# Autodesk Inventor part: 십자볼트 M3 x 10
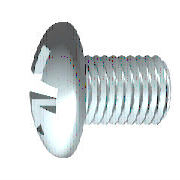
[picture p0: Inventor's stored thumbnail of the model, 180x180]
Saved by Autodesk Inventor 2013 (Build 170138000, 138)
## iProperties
IsCustomPart: 0
Created: 2012-02
Part Number: 십자볼트 M3 x 10
Material: 스테인리스강
Description: 십자 오목 머리 나사
Document SubType Name: Modeling
Standard: KS B 1023
Designer: mduedu
Standards Organization: KS
Language: ko-KR
Size Designation: A  M 3 x 10 - H
Categories: <MemberInstance><Categories><Category DisplayName="조임쇠" InternalName="e4da775c-781d-43d5-af7c-5136215cf5a6" Mnemonic="FSTN"><Category DisplayName="볼트" InternalN
Density: 1 g/cm^3
Author: mduedu
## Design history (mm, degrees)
body "Solid1"
workplane "Work Plane3"
sketch "스케치2"
  geometry: L1 (-3.72, 0)-(3.72, 0) reference; L2 (0, -3.72)-(0, 3.72) reference; L3 (0, 1.5)-(0, 0); L4 (0, 0)-(1.5, 0); L5 (0, 0)-(1.879, 1.879); L6 (0.253, 1.479)-(0.261, 0.456); L7 (1.479, 0.253)-(0.456, 0.261); L8 (0.253, -1.479)-(0.261, -0.456); L9 (1.479, -0.253)-(0.456, -0.261); L10 (-0.253, 1.479)-(-0.261, 0.456); L11 (-1.479, 0.253)-(-0.456, 0.261); L12 (-1.479, -0.253)-(-0.456, -0.261); L13 (-0.253, -1.479)-(-0.261, -0.456); A1 r 0.45 centre (0, 0) between (0.45, 0) and (0, 0.45); A2 r 1.5 centre (0, 0) between (1.5, 0) and (1.479, 0.253); A3 r 1.5 centre (0, 0) between (0.253, 1.479) and (0, 1.5); A4 r 1.5 centre (0, 0) between (1.479, 0.253) and (0.253, 1.479); A5 r 1.5 centre (0, 0) between (0, -1.5) and (0.253, -1.479); A6 r 1.5 centre (0, 0) between (0.253, -1.479) and (1.479, -0.253); A7 r 1.5 centre (0, 0) between (1.479, -0.253) and (1.5, 0); A8 r 1.5 centre (0, 0) between (-1.479, 0.253) and (-1.5, 0); A9 r 1.5 centre (0, 0) between (-0.253, 1.479) and (-1.479, 0.253); A10 r 1.5 centre (0, 0) between (0, 1.5) and (-0.253, 1.479); A11 r 1.5 centre (0, 0) between (-1.5, 0) and (-1.479, -0.253); A12 r 1.5 centre (0, 0) between (-1.479, -0.253) and (-0.253, -1.479); A13 r 1.5 centre (0, 0) between (-0.253, -1.479) and (0, -1.5); A14 r 0.525 centre (0, 0) between (0.525, 0) and (0, 0.525); A15 r 0.197 centre (0.457, 0.457) between (0.261, 0.456) and (0.456, 0.261); A16 r 0.197 centre (0.457, -0.457) between (0.456, -0.261) and (0.261, -0.456); A17 r 0.197 centre (-0.457, 0.457) between (-0.456, 0.261) and (-0.261, 0.456); A18 r 0.197 centre (-0.457, -0.457) between (-0.261, -0.456) and (-0.456, -0.261); 1 further point
  constraints: 38 point on circle, 22 end point, 19 symmetric about line, 18 centre point, 4 coincident, 3 collinear, 3 point on line, 3 tangent, 1 perpendicular, 21 other
  dimensions: "d4" = 45 deg angle of L5 L4; "d5" = 0.9 diameter of A1 (= 0.3 x SDM); "d6" = 3 diameter of A4 (= SDM); "d7" = 0.2525 distance from line of L6.start L3 (= 0.5 x SBR); "d14" = 1.05 diameter of A14 (= 0.35 x SDM)
extrude "슬롯" join sketch "스케치2" taper "d15" = 5 deg; stored distance "d54" = 10
revolve "절단부" stored, may be unused: angle "d56" = 90 deg
revolve "본체" stored, may be unused: angle "d18" = 90 deg
workplane "Work Plane1"
sketch "스케치1"
  geometry: L1 (10, 0)-(10, 1.5); L2 (10, 1.5)-(1, 1.5); L3 (3.962, 5.08)-(3.962, 5.08); L4 (-2.4, 0)-(-2.4, 2.59); L5 (-2.2, 1.4)-(-1.036, 0.82); L6 (-1.036, 0.82)-(-0.6, 0); L7 (-0.6, 0)-(10, 0); L8 (-5.105, 0)-(12.517, 0) reference; L9 (0, -1.016)-(0, 6.096) reference; L10 (-2.2, 1.4)-(-2.4, 1.5); L11 (-1.636, 2.657)-(-2.4, 2.59); L12 (-1.636, 2.657)-(0, 2.8); L13 (0, 2.8)-(0, 1.347); L14 (0, 1.347)-(0.693, 1.347); L15 (0.693, 1.347)-(1, 1.5); L16 (1, 1.5)-(0, 1.5); A1 r 5 centre (2.6, 0) between (-1.636, 2.657) and (-2.4, 0)
  constraints: 28 end point, 5 point on line, 4 collinear, 4 point on circle, 3 parallel, 2 perpendicular, 1 centre point, 1 horizontal, 1 tangent
  dimensions: "d1" = 3 diameter of L2 L7 (= GD); "d2" = 1.8 distance from line of L6.end L4 (= STI); "d11" = 3 diameter of L10.end L7 (= SDM); "d12" = 62 deg angle of L6 L7; "d13" = 26.5 deg angle of L5 L7; "d17" = 5.6 diameter of L12.end L7 (= KOD); "d19" = 5 deg angle of L12 L7 (= KEWI); "d20" = 2.4 distance between parallel lines of L4 L13 (= KOH); "d21" = 5 radius of A1 (= KR); "d23" = 2.6935 diameter of L14 L7 (= BDM); "d24" = 9 distance of L1.end L2.end (= GEL); "d25" = 0.30673 horizontal distance of L14.end L2.end (= GAL); "d28" = 10 distance between parallel lines of L1 L13 (= NLG)
fillet "모깎기1" dims "d29" = 1.2 (= RR)
fillet "모깎기2" dims "d16" = 0.101 (= 0.2 x SBR)
feature "스레드" dims "d8" = 9 (= GEL), "d9" = 0
chamfer "모따기1" distance "d26" = 0.30673 (= -0.5 x SPD + 0.5 x GD); stored, may be unused: second distance "d27" = 0.30683 (computed from GUL), angle "d78" = 45 deg
other parameters: "GD" = 3 (= NND) [user parameter; used in 2 equation terms], "NLG" = 10 [user parameter; used in 1 equation term], "GEL" = 9 [user parameter; used in 2 equation terms], "KOD" = 5.6 [user parameter; used in 1 equation term], "KOH" = 2.4 [user parameter; used in 2 equation terms], "SDM" = 3 [user parameter; used in 4 equation terms], "STI" = 1.8 [user parameter; used in 1 equation term], "SBR" = 0.505 [user parameter; used in 2 equation terms], "GAL" = 0.30673 (= 0.61345 x PTC) [user parameter; used in 1 equation term], "SPD" = 2.38655 (= NND - 1.2269 x PTC) [user parameter; used in 1 equation term], "KEWI" = 5 deg [user parameter; used in 1 equation term], "d3" = -2.4 (= -KOH), "d10" = 0, "KR" = 5 [user parameter; used in 1 equation term], "BDM" = 2.6935 [user parameter; used in 1 equation term], "GUL" = 0.30673 (= 0.61345 x PTC) [user parameter; used in 1 equation term], "RR" = 1.2 [user parameter; used in 1 equation term], "d79" = 0, "d80" = 0, "PTC" = 0.5 [user parameter; used in 5 equation terms], "THREADDIA" = 3 [user parameter; used in 1 equation term], "TOA" = 30 deg [user parameter], "NND" = 3 [user parameter; used in 2 equation terms], "GD1" = 2.38655 (= THREADDIA - 1.2269 x PTC) [user parameter]
